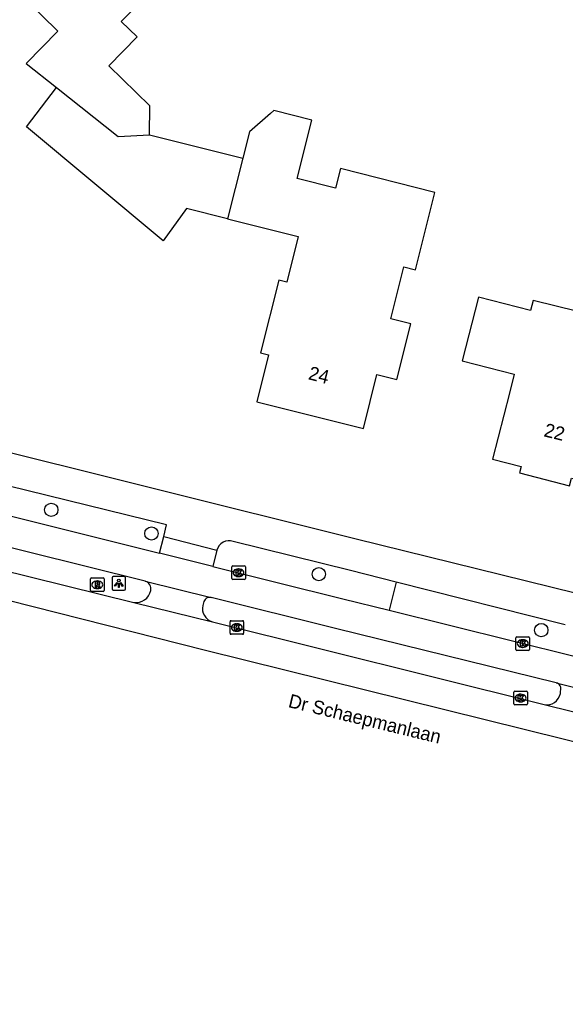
# Model space of a CAD drawing. Extents: x 161354 to 161876, y 382161 to 382804.
# Drawn here: x 161439.4 to 161479.4, y 382164.9 to 382237.9 of the extents above; entities that cross this region are included whole.
import ezdxf

# ---------------------------------------------------------------- set-up
doc = ezdxf.new("R2010")
doc.units = 0
for name, color, linetype in [('IMGEO_Berm_groen', 7, 'Continuous'), ('IMGEO_Boom', 7, 'Continuous'), ('IMGEO_Fietspad_gesloten', 7, 'Continuous'), ('IMGEO_Kolk', 7, 'Continuous'), ('IMGEO_Lichtpunt', 7, 'Continuous'), ('IMGEO_Openbare_ruimte_label', 7, 'Continuous'), ('IMGEO_Pand', 7, 'Continuous'), ('IMGEO_Pand_nummerreeks', 7, 'Continuous'), ('IMGEO_Parkeervlak_gesloten', 7, 'Continuous'), ('IMGEO_Rijbaan_lokaal_gesloten', 7, 'Continuous'), ('IMGEO_Rioolput', 7, 'Continuous'), ('IMGEO_Voetpad_open', 7, 'Continuous')]:
    doc.layers.add(name, color=color, linetype=linetype)

msp = doc.modelspace()

# ---------------------------------------------------------------- linework, layer by layer
at = {"layer": 'IMGEO_Berm_groen'}
msp.add_lwpolyline([(161467.037, 382196.636), (161466.523, 382194.566)], dxfattribs=at)
at = {"layer": 'IMGEO_Boom'}
for centre in [(161441.737, 382201.935), (161449.082, 382200.197), (161461.363, 382197.214), (161477.687, 382193.109)]:
    msp.add_circle(centre, 0.489, dxfattribs=at)
at = {"layer": 'IMGEO_Fietspad_gesloten'}
for points in [[(161448.631, 382196.696), (161418.403, 382204.211)], [(161438.04, 382201.653), (161449.683, 382198.752)], [(161453.587, 382197.783), (161449.683, 382198.752)], [(161453.587, 382197.783), (161463.127, 382195.408), (161466.523, 382194.566)], [(161448.631, 382196.696), (161453.454, 382195.498)], [(161478.779, 382189.246), (161462.581, 382193.233), (161453.454, 382195.498)], [(161466.523, 382194.566), (161480.111, 382191.197)], [(161478.779, 382189.246), (161484.015, 382187.92)]]:
    msp.add_lwpolyline(points, dxfattribs=at)
at = {"layer": 'IMGEO_Kolk'}
for p, q in [((161454.971, 382196.894), (161454.971, 382197.746)), ((161455.046, 382197.82), (161455.898, 382197.82)), ((161455.459, 382197.6), (161455.484, 382197.6)), ((161455.972, 382197.746), (161455.972, 382196.894)), ((161455.898, 382196.82), (161455.046, 382196.82)), ((161455.482, 382197.04), (161455.457, 382197.04)), ((161454.847, 382192.872), (161454.847, 382193.724)), ((161454.922, 382193.798), (161455.774, 382193.798)), ((161455.848, 382193.724), (161455.848, 382192.872)), ((161455.358, 382193.018), (161455.333, 382193.018)), ((161455.335, 382193.578), (161455.36, 382193.578)), ((161455.774, 382192.798), (161454.922, 382192.798)), ((161475.829, 382191.696), (161475.829, 382192.548)), ((161475.904, 382192.622), (161476.756, 382192.622)), ((161476.317, 382192.402), (161476.342, 382192.402)), ((161476.83, 382192.548), (161476.83, 382191.696)), ((161476.756, 382191.622), (161475.904, 382191.622)), ((161476.34, 382191.842), (161476.315, 382191.842)), ((161475.667, 382187.699), (161475.667, 382188.551)), ((161475.742, 382188.625), (161476.594, 382188.625)), ((161476.668, 382188.551), (161476.668, 382187.699)), ((161476.178, 382187.845), (161476.153, 382187.845)), ((161476.155, 382188.405), (161476.18, 382188.405)), ((161476.594, 382187.625), (161475.742, 382187.625))]:
    msp.add_line(p, q, dxfattribs=at)
for points in [[(161454.971, 382196.894), (161454.971, 382197.746)], [(161455.046, 382197.82), (161455.898, 382197.82)], [(161455.292, 382197.52), (161455.415, 382197.52), (161455.415, 382197.369), (161455.545, 382197.52), (161455.709, 382197.52), (161455.563, 382197.369), (161455.716, 382197.12), (161455.564, 382197.12), (161455.479, 382197.284), (161455.415, 382197.217), (161455.415, 382197.12), (161455.292, 382197.12), (161455.292, 382197.52)], [(161455.972, 382197.746), (161455.972, 382196.894)], [(161455.898, 382196.82), (161455.046, 382196.82)], [(161454.847, 382192.872), (161454.847, 382193.724)], [(161454.922, 382193.798), (161455.774, 382193.798)], [(161455.848, 382193.724), (161455.848, 382192.872)], [(161455.168, 382193.498), (161455.291, 382193.498), (161455.291, 382193.347), (161455.421, 382193.498), (161455.585, 382193.498), (161455.439, 382193.347), (161455.592, 382193.098), (161455.44, 382193.098), (161455.355, 382193.262), (161455.291, 382193.195), (161455.291, 382193.098), (161455.168, 382193.098), (161455.168, 382193.498)], [(161455.774, 382192.798), (161454.922, 382192.798)], [(161475.829, 382191.696), (161475.829, 382192.548)], [(161475.904, 382192.622), (161476.756, 382192.622)], [(161476.15, 382192.322), (161476.273, 382192.322), (161476.273, 382192.171), (161476.403, 382192.322), (161476.567, 382192.322), (161476.421, 382192.171), (161476.574, 382191.922), (161476.422, 382191.922), (161476.337, 382192.086), (161476.273, 382192.019), (161476.273, 382191.922), (161476.15, 382191.922), (161476.15, 382192.322)], [(161476.83, 382192.548), (161476.83, 382191.696)], [(161476.756, 382191.622), (161475.904, 382191.622)], [(161475.667, 382187.699), (161475.667, 382188.551)], [(161475.742, 382188.625), (161476.594, 382188.625)], [(161476.668, 382188.551), (161476.668, 382187.699)], [(161475.988, 382188.325), (161476.111, 382188.325), (161476.111, 382188.174), (161476.241, 382188.325), (161476.405, 382188.325), (161476.259, 382188.174), (161476.412, 382187.925), (161476.26, 382187.925), (161476.175, 382188.089), (161476.111, 382188.022), (161476.111, 382187.925), (161475.988, 382187.925), (161475.988, 382188.325)], [(161476.594, 382187.625), (161475.742, 382187.625)]]:
    msp.add_lwpolyline(points, dxfattribs=at)
for centre, start, end in [((161455.048, 382197.744), 91.55205, 178.44795), ((161455.048, 382197.744), 91.55205, 178.44795), ((161455.896, 382197.744), 1.55205, 88.44795), ((161455.896, 382197.744), 1.55205, 88.44795), ((161455.048, 382196.896), 181.55205, 268.44795), ((161455.048, 382196.896), 181.55205, 268.44795), ((161455.896, 382196.896), 271.55205, 358.44795), ((161455.896, 382196.896), 271.55205, 358.44795), ((161454.924, 382193.722), 91.55205, 178.44795), ((161454.924, 382193.722), 91.55205, 178.44795), ((161455.772, 382193.722), 1.55205, 88.44795), ((161455.772, 382193.722), 1.55205, 88.44795), ((161454.924, 382192.874), 181.55205, 268.44795), ((161454.924, 382192.874), 181.55205, 268.44795), ((161455.772, 382192.874), 271.55205, 358.44795), ((161455.772, 382192.874), 271.55205, 358.44795), ((161475.906, 382192.546), 91.55205, 178.44795), ((161475.906, 382192.546), 91.55205, 178.44795), ((161476.754, 382192.546), 1.55205, 88.44795), ((161476.754, 382192.546), 1.55205, 88.44795), ((161475.906, 382191.698), 181.55205, 268.44795), ((161475.906, 382191.698), 181.55205, 268.44795), ((161476.754, 382191.698), 271.55205, 358.44795), ((161476.754, 382191.698), 271.55205, 358.44795), ((161475.744, 382188.549), 91.55205, 178.44795), ((161475.744, 382188.549), 91.55205, 178.44795), ((161476.592, 382188.549), 1.55205, 88.44795), ((161476.592, 382188.549), 1.55205, 88.44795), ((161475.744, 382187.701), 181.55205, 268.44795), ((161475.744, 382187.701), 181.55205, 268.44795), ((161476.592, 382187.701), 271.55205, 358.44795), ((161476.592, 382187.701), 271.55205, 358.44795)]:
    msp.add_arc(centre, 0.0765, start, end, dxfattribs=at)
for centre, major_axis, ratio, start_param, end_param in [((161455.458, 382197.32), (-0.387, 0.002), 0.722429, 4.712389, 7.853982), ((161455.483, 382197.32), (-0.39, 0.002), 0.717154, 1.570796, 4.712389), ((161455.334, 382193.298), (-0.387, 0.002), 0.722429, 4.712389, 7.853982), ((161455.359, 382193.298), (-0.39, 0.002), 0.717154, 1.570796, 4.712389), ((161476.316, 382192.122), (-0.387, 0.002), 0.722429, 4.712389, 7.853982), ((161476.341, 382192.122), (-0.39, 0.002), 0.717154, 1.570796, 4.712389), ((161476.154, 382188.125), (-0.387, 0.002), 0.722429, 4.712389, 7.853982), ((161476.179, 382188.125), (-0.39, 0.002), 0.717154, 1.570796, 4.712389)]:
    msp.add_ellipse(centre, major_axis=major_axis, ratio=ratio, start_param=start_param, end_param=end_param, dxfattribs=at)
at = {"layer": 'IMGEO_Lichtpunt'}
for p, q in [((161446.19, 382196.946), (161446.19, 382196.139)), ((161446.19, 382196.946), (161446.19, 382196.139)), ((161447.092, 382197.041), (161446.284, 382197.041)), ((161447.092, 382197.041), (161446.284, 382197.041)), ((161447.186, 382196.139), (161447.186, 382196.946)), ((161447.186, 382196.139), (161447.186, 382196.946)), ((161446.284, 382196.045), (161447.092, 382196.045)), ((161446.284, 382196.045), (161447.092, 382196.045))]:
    msp.add_line(p, q, dxfattribs=at)
for points in [[(161446.564, 382196.61), (161446.603, 382196.582), (161446.415, 382196.32), (161446.377, 382196.347), (161446.564, 382196.61)], [(161446.666, 382196.562), (161446.713, 382196.562), (161446.713, 382196.24), (161446.666, 382196.24), (161446.666, 382196.562)], [(161446.776, 382196.582), (161446.814, 382196.609), (161447.001, 382196.347), (161446.962, 382196.319), (161446.776, 382196.582)]]:
    msp.add_lwpolyline(points, dxfattribs=at)
msp.add_circle((161446.689, 382196.744), 0.0994, dxfattribs=at)
for centre, start, end in [((161446.284, 382196.946), 90, 180), ((161446.284, 382196.946), 90, 180), ((161447.092, 382196.946), 0, 90), ((161447.092, 382196.946), 0, 90), ((161446.284, 382196.139), 180, 270), ((161446.284, 382196.139), 180, 270), ((161447.092, 382196.139), 270, 0), ((161447.092, 382196.139), 270, 360)]:
    msp.add_arc(centre, 0.0946, start, end, dxfattribs=at)
at = {"layer": 'IMGEO_Pand'}
for points in [[(161448.936, 382229.455), (161448.963, 382231.58), (161445.96, 382234.517), (161448.03, 382236.632), (161446.864, 382237.771), (161449.8, 382240.772), (161441.188, 382249.2), (161440.835, 382248.84), (161440.343, 382249.322), (161438.55, 382247.491), (161438.994, 382247.056), (161435.79, 382243.781), (161437.657, 382241.954), (161437.441, 382241.734), (161442.21, 382237.067), (161439.89, 382234.697), (161442.119, 382232.914)], [(161454.665, 382223.288), (161451.662, 382224.041), (161449.949, 382221.677), (161439.919, 382230.035), (161442.119, 382232.914)], [(161442.119, 382232.914), (161446.641, 382229.335), (161448.936, 382229.455)], [(161454.665, 382223.288), (161459.848, 382221.99), (161459.01, 382218.643), (161458.418, 382218.791), (161457.082, 382213.456), (161457.674, 382213.308), (161456.81, 382209.857), (161464.635, 382207.897), (161465.626, 382211.853), (161467.091, 382211.487), (161468.118, 382215.59), (161466.653, 382215.957), (161467.608, 382219.769), (161468.463, 382219.553), (161469.884, 382225.231), (161462.946, 382226.983), (161462.583, 382225.533), (161459.78, 382226.235), (161460.857, 382230.536), (161458.063, 382231.236), (161457.808, 382231.015), (161456.266, 382229.681), (161455.78, 382227.741)], [(161448.936, 382229.455), (161455.78, 382227.741)], [(161455.78, 382227.741), (161454.665, 382223.288)], [(161484.459, 382225.785), (161481.965, 382216.09), (161477.091, 382217.295), (161476.9, 382216.551), (161473.081, 382217.533), (161471.884, 382212.879), (161475.703, 382211.897), (161475.345, 382210.506), (161474.099, 382205.663), (161476.213, 382205.119), (161476.089, 382204.639), (161479.751, 382203.697), (161479.893, 382204.252), (161481.938, 382203.726), (161484.914, 382215.295), (161489.341, 382214.202), (161491.85, 382223.959), (161484.459, 382225.785)]]:
    msp.add_lwpolyline(points, dxfattribs=at)
at = {"layer": 'IMGEO_Parkeervlak_gesloten'}
for points in [[(161427.287, 382198.569), (161429.682, 382199.431), (161429.995, 382199.482), (161430.279, 382199.461), (161447.783, 382195.136)], [(161453.562, 382193.718), (161477.906, 382187.637)]]:
    msp.add_lwpolyline(points, dxfattribs=at)
at = {"layer": 'IMGEO_Rijbaan_lokaal_gesloten'}
msp.add_lwpolyline([(161562.35, 382164.929), (161553.188, 382166.887), (161517.576, 382175.615), (161453.047, 382191.62), (161425.904, 382198.493)], dxfattribs=at)
at = {"layer": 'IMGEO_Rioolput'}
for p, q in [((161444.606, 382196.012), (161444.606, 382196.864)), ((161444.681, 382196.938), (161445.533, 382196.938)), ((161445.094, 382196.718), (161445.119, 382196.718)), ((161445.607, 382196.864), (161445.607, 382196.012)), ((161445.533, 382195.938), (161444.681, 382195.938)), ((161445.117, 382196.158), (161445.092, 382196.158))]:
    msp.add_line(p, q, dxfattribs=at)
for points in [[(161444.606, 382196.012), (161444.606, 382196.864)], [(161444.681, 382196.938), (161445.533, 382196.938)], [(161445.195, 382196.636), (161444.943, 382196.638), (161444.943, 382196.238)], [(161445.121, 382196.557), (161445.067, 382196.557), (161445.067, 382196.476)], [(161445.607, 382196.864), (161445.607, 382196.012)], [(161445.533, 382195.938), (161444.681, 382195.938)], [(161444.943, 382196.238), (161445.067, 382196.238), (161445.067, 382196.4), (161445.078, 382196.4)], [(161445.067, 382196.476), (161445.119, 382196.476)], [(161445.125, 382196.371), (161445.196, 382196.238), (161445.336, 382196.238), (161445.271, 382196.364)]]:
    msp.add_lwpolyline(points, dxfattribs=at)
for centre, radius, start, end in [((161444.683, 382196.862), 0.0765, 91.55205, 178.44795), ((161444.683, 382196.862), 0.0765, 91.55205, 178.44795), ((161445.127, 382196.461), 0.0964, 77.00612, 93.18647), ((161445.141, 382196.518), 0.0378, 276.66336, 79.67722), ((161445.194, 382196.526), 0.109, 350.36119, 89.41601), ((161445.531, 382196.862), 0.0765, 1.55205, 88.44795), ((161445.531, 382196.862), 0.0765, 1.55205, 88.44795), ((161444.683, 382196.014), 0.0765, 181.55205, 268.44795), ((161444.683, 382196.014), 0.0765, 181.55205, 268.44795), ((161445.077, 382196.347), 0.0533, 26.02933, 88.69889), ((161445.103, 382196.665), 0.19, 274.7715, 282.96867), ((161445.192, 382196.526), 0.112, 277.58423, 350.98172), ((161445.176, 382196.311), 0.108, 29.51342, 73.79051), ((161445.531, 382196.014), 0.0765, 271.55205, 358.44795), ((161445.531, 382196.014), 0.0765, 271.55205, 358.44795)]:
    msp.add_arc(centre, radius, start, end, dxfattribs=at)
for centre, major_axis, ratio, start_param, end_param in [((161445.093, 382196.438), (-0.387, 0.002), 0.722429, 4.712389, 7.853982), ((161445.118, 382196.438), (-0.39, 0.002), 0.717154, 1.570796, 4.712389)]:
    msp.add_ellipse(centre, major_axis=major_axis, ratio=ratio, start_param=start_param, end_param=end_param, dxfattribs=at)
at = {"layer": 'IMGEO_Voetpad_open'}
for points in [[(161540.678, 382180.901), (161500, 382190.938), (161464.013, 382199.817), (161420.378, 382210.687)], [(161449.987, 382199.986), (161450.193, 382200.822), (161438.548, 382203.693)], [(161449.683, 382198.752), (161449.987, 382199.986)], [(161449.987, 382199.986), (161453.883, 382198.974)], [(161467.037, 382196.636), (161463.694, 382197.481), (161455.074, 382199.619)], [(161453.883, 382198.974), (161453.587, 382197.783)], [(161479.435, 382193.502), (161467.037, 382196.636)], [(161447.783, 382195.136), (161453.562, 382193.718)], [(161452.897, 382195.117), (161452.854, 382194.921)], [(161479.085, 382188.453), (161479.101, 382188.624)], [(161477.906, 382187.637), (161484.029, 382186.14)]]:
    msp.add_lwpolyline(points, dxfattribs=at)
for centre, radius, start, end in [((161454.782, 382198.737), 0.929, 71.66678, 165.20978), ((161448.445, 382196.132), 0.594, 348.61678, 71.73904), ((161447.948, 382196.222), 1.099, 261.37224, 349.11718), ((161453.359, 382195.039), 0.469, 78.36439, 170.38155), ((161453.83, 382194.686), 1.004, 166.44669, 254.50938), ((161478.658, 382188.789), 0.473, 339.56867, 75.17117), ((161478.082, 382188.642), 1.02, 260.04887, 349.32627)]:
    msp.add_arc(centre, radius, start, end, dxfattribs=at)

# ---------------------------------------------------------------- texts
at = {"layer": 'IMGEO_Openbare_ruimte_label'}
msp.add_text('Dr Schaepmanlaan', height=1, rotation=346.35276, dxfattribs=at).set_placement((161459.063, 382187.467))
at = {"layer": 'IMGEO_Pand_nummerreeks'}
for s, rotation, p in [('24', 345.93962, (161460.533, 382211.522)), ('22', 346.12296, (161477.818, 382207.339))]:
    msp.add_text(s, height=1, rotation=rotation, dxfattribs=at).set_placement(p)

doc.saveas('drawing.dxf')
